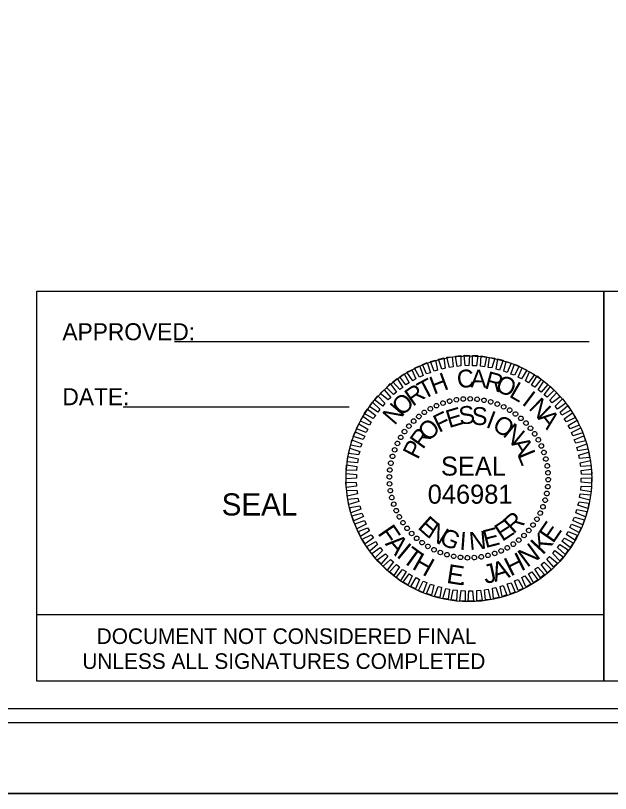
# Model space of a CAD drawing. Extents: x 198 to 2213, y -571 to 529.
# Drawn here: x 1292.9 to 1502.9, y -570.9 to -296.6 of the extents above; entities that cross this region are included whole.
import ezdxf

# ---------------------------------------------------------------- set-up
doc = ezdxf.new("R2010")
doc.units = 0
for name, color, linetype in [('DEV TRANSPORTATION OPERATIONS PLAN SHEET', 7, 'Continuous'), ('P_RDY_Terminator_Cell', 7, 'Continuous'), ('Sheet Data Field CELL', 7, 'Continuous'), ('Sheet PE Seal CELL', 7, 'Continuous'), ('Sheet_Title_CELL', 7, 'Continuous')]:
    doc.layers.add(name, color=color, linetype=linetype)

msp = doc.modelspace()

# ---------------------------------------------------------------- linework, layer by layer
at = {"layer": 'DEV TRANSPORTATION OPERATIONS PLAN SHEET'}
for p, q in [((1443.71, -433.19), (1443.71, -433.19)), ((1446.05, -432.52), (1446.05, -432.52)), ((1448.51, -432.07), (1448.51, -432.07)), ((1450.92, -431.74), (1450.92, -431.74)), ((1453.37, -431.68), (1453.37, -431.68)), ((1455.83, -431.85), (1455.83, -431.85)), ((1458.24, -432.24), (1458.24, -432.24)), ((1460.58, -432.74), (1460.58, -432.74)), ((1439.29, -435.2), (1439.29, -435.2)), ((1441.47, -434.09), (1441.47, -434.09)), ((1462.93, -433.53), (1462.93, -433.53)), ((1465.17, -434.53), (1465.17, -434.53)), ((1467.34, -435.65), (1467.34, -435.65)), ((1435.21, -437.89), (1435.21, -437.89)), ((1437.17, -436.49), (1437.17, -436.49)), ((1469.36, -437.05), (1469.36, -437.05)), ((1471.31, -438.56), (1471.31, -438.56)), ((1431.69, -441.29), (1431.69, -441.29)), ((1433.37, -439.56), (1433.37, -439.56)), ((1473.04, -440.23), (1473.04, -440.23)), ((1430.18, -443.25), (1430.18, -443.25)), ((1474.72, -442.08), (1474.72, -442.08)), ((1476.12, -444.03), (1476.12, -444.03)), ((1428.79, -445.26), (1428.79, -445.26)), ((1477.4, -446.16), (1477.4, -446.16)), ((1426.66, -449.68), (1426.66, -449.68)), ((1427.67, -447.44), (1427.67, -447.44)), ((1478.52, -448.34), (1478.52, -448.34)), ((1425.88, -452.02), (1425.88, -452.02)), ((1479.42, -450.57), (1479.42, -450.57)), ((1425.38, -454.37), (1425.38, -454.37)), ((1480.09, -452.92), (1480.09, -452.92)), ((1424.99, -456.77), (1424.99, -456.77)), ((1480.53, -455.38), (1480.53, -455.38)), ((1480.87, -457.78), (1480.87, -457.78)), ((1424.82, -459.23), (1424.82, -459.23)), ((1452.87, -459.74), (1452.87, -459.74)), ((1480.92, -460.24), (1480.92, -460.24)), ((1424.87, -461.69), (1424.87, -461.69)), ((1480.76, -462.7), (1480.76, -462.7)), ((1425.21, -464.09), (1425.21, -464.09)), ((1480.37, -465.1), (1480.37, -465.1)), ((1425.66, -466.55), (1425.66, -466.55)), ((1426.33, -468.9), (1426.33, -468.9)), ((1479.86, -467.45), (1479.86, -467.45)), ((1427.22, -471.14), (1427.22, -471.14)), ((1479.08, -469.79), (1479.08, -469.79)), ((1428.34, -473.31), (1428.34, -473.31)), ((1476.96, -474.21), (1476.96, -474.21)), ((1478.07, -472.03), (1478.07, -472.03)), ((1429.62, -475.44), (1429.62, -475.44)), ((1475.56, -476.22), (1475.56, -476.22)), ((1431.02, -477.39), (1431.02, -477.39)), ((1432.7, -479.24), (1432.7, -479.24)), ((1472.37, -479.91), (1472.37, -479.91)), ((1474.05, -478.18), (1474.05, -478.18)), ((1434.43, -480.91), (1434.43, -480.91)), ((1436.39, -482.42), (1436.39, -482.42)), ((1470.53, -481.59), (1470.53, -481.59)), ((1438.4, -483.82), (1438.4, -483.82)), ((1440.58, -484.94), (1440.58, -484.94)), ((1464.27, -485.39), (1464.27, -485.39)), ((1466.45, -484.27), (1466.45, -484.27)), ((1468.57, -482.98), (1468.57, -482.98)), ((1442.81, -485.94), (1442.81, -485.94)), ((1445.16, -486.73), (1445.16, -486.73)), ((1447.51, -487.23), (1447.51, -487.23)), ((1449.91, -487.62), (1449.91, -487.62)), ((1452.37, -487.79), (1452.37, -487.79)), ((1454.83, -487.73), (1454.83, -487.73)), ((1457.23, -487.4), (1457.23, -487.4)), ((1459.69, -486.95), (1459.69, -486.95)), ((1462.04, -486.28), (1462.04, -486.28))]:
    msp.add_line(p, q, dxfattribs=at)
for points in [[(1446.05, -420.62), (1445.16, -417.04), (1447, -416.87), (1447.39, -420.45)], [(1448.74, -420.28), (1448.12, -416.71), (1450.02, -416.48), (1450.08, -420.11)], [(1451.53, -420), (1451.25, -416.37), (1453.09, -416.43), (1452.87, -420.06)], [(1454.21, -420.06), (1454.21, -416.43), (1456.06, -416.48), (1455.55, -420.11)], [(1457.01, -420.23), (1457.23, -416.59), (1459.07, -416.93), (1458.35, -420.45)], [(1437.95, -422.85), (1436.5, -419.61), (1438.17, -418.94), (1439.35, -422.52)], [(1440.69, -421.96), (1439.4, -418.61), (1441.14, -418.1), (1441.86, -421.57)], [(1443.37, -421.23), (1442.2, -417.71), (1444.1, -417.32), (1444.54, -420.95)], [(1459.69, -420.67), (1460.19, -417.1), (1462.04, -417.38), (1461.03, -420.84)], [(1462.54, -421.29), (1463.1, -417.66), (1465, -418.1), (1463.71, -421.57)], [(1465.22, -422.01), (1466.06, -418.55), (1467.79, -419.11), (1466.39, -422.41)], [(1467.74, -423.02), (1469.02, -419.5), (1470.59, -420.17), (1469.02, -423.41)], [(1433.09, -425.37), (1431.02, -422.35), (1432.75, -421.46), (1434.15, -424.7)], [(1435.49, -424.03), (1433.7, -420.9), (1435.44, -420.11), (1436.72, -423.52)], [(1470.25, -424.08), (1471.65, -420.79), (1473.38, -421.57), (1471.48, -424.7)], [(1472.82, -425.37), (1474.33, -422.18), (1476.01, -423.13), (1473.88, -426.04)], [(1428.51, -428.44), (1426.1, -425.76), (1427.61, -424.59), (1429.57, -427.71)], [(1430.63, -426.76), (1428.56, -423.91), (1430.02, -422.85), (1431.86, -426.09)], [(1475, -426.88), (1476.96, -423.64), (1478.41, -424.81), (1476.23, -427.55)], [(1426.27, -430.17), (1423.81, -427.71), (1425.15, -426.37), (1427.33, -429.39)], [(1477.29, -428.55), (1479.36, -425.48), (1480.81, -426.71), (1478.35, -429.34)], [(1479.42, -430.29), (1481.71, -427.38), (1483.05, -428.72), (1480.48, -431.12)], [(1422.47, -434.25), (1419.57, -432.07), (1420.79, -430.62), (1423.25, -433.25)], [(1424.43, -432.13), (1421.58, -429.84), (1422.97, -428.55), (1425.32, -431.24)], [(1481.43, -432.24), (1483.83, -429.61), (1485.17, -430.96), (1482.27, -433.14)], [(1420.79, -436.38), (1417.78, -434.48), (1418.84, -432.86), (1421.52, -435.31)], [(1483.38, -434.25), (1485.95, -431.74), (1487.13, -433.25), (1484.17, -435.37)], [(1419.12, -438.61), (1415.99, -436.94), (1417.11, -435.37), (1420.01, -437.61)], [(1485.06, -436.43), (1487.8, -434.09), (1488.86, -435.71), (1485.73, -437.49)], [(1417.78, -441.01), (1414.59, -439.62), (1415.43, -437.89), (1418.45, -439.95)], [(1486.51, -438.72), (1489.47, -436.6), (1490.54, -438.28), (1487.29, -439.84)], [(1416.66, -443.59), (1413.19, -442.3), (1414.03, -440.57), (1417.22, -442.36)], [(1487.97, -441.18), (1491.09, -439.23), (1491.82, -440.96), (1488.64, -442.24)], [(1415.54, -446.04), (1412.08, -445.04), (1412.8, -443.31), (1416.16, -444.87)], [(1489.08, -443.59), (1492.38, -441.91), (1493.11, -443.7), (1489.64, -444.81)], [(1414.7, -448.73), (1411.24, -448), (1411.63, -446.16), (1415.15, -447.55)], [(1490.09, -446.21), (1493.5, -444.76), (1494.11, -446.49), (1490.65, -447.39)], [(1413.98, -451.41), (1410.51, -450.96), (1410.9, -449.06), (1414.42, -450.24)], [(1490.98, -448.89), (1494.56, -447.61), (1494.89, -449.45), (1491.37, -450.07)], [(1413.53, -454.26), (1409.95, -453.92), (1410.18, -452.02), (1413.81, -452.92)], [(1491.65, -451.58), (1495.17, -450.51), (1495.51, -452.41), (1491.99, -452.75)], [(1413.25, -456.94), (1409.62, -456.83), (1409.73, -454.99), (1413.36, -455.6)], [(1492.16, -454.26), (1495.79, -453.48), (1495.96, -455.38), (1492.38, -455.6)], [(1413.19, -459.74), (1409.56, -459.9), (1409.56, -458), (1413.19, -458.39)], [(1492.49, -456.94), (1496.12, -456.49), (1496.24, -458.39), (1492.6, -458.28)], [(1492.55, -459.74), (1496.18, -459.57), (1496.18, -461.47), (1492.55, -461.08)], [(1413.25, -462.53), (1409.62, -462.98), (1409.51, -461.08), (1413.14, -461.19)], [(1492.49, -462.53), (1496.12, -462.64), (1496.01, -464.49), (1492.38, -463.87)], [(1413.59, -465.21), (1409.95, -465.99), (1409.79, -464.09), (1413.36, -463.87)], [(1492.21, -465.21), (1495.79, -465.55), (1495.57, -467.45), (1491.93, -466.55)], [(1414.09, -467.89), (1410.57, -468.96), (1410.23, -467.06), (1413.75, -466.72)], [(1491.77, -468.06), (1495.23, -468.51), (1494.84, -470.41), (1491.32, -469.24)], [(1414.76, -470.58), (1411.18, -471.86), (1410.85, -470.02), (1414.37, -469.4)], [(1491.04, -470.74), (1494.5, -471.47), (1494.11, -473.31), (1490.59, -471.92)], [(1415.65, -473.26), (1412.24, -474.71), (1411.63, -472.98), (1415.09, -472.09)], [(1490.2, -473.43), (1493.67, -474.43), (1492.94, -476.16), (1489.59, -474.6)], [(1416.66, -475.89), (1413.36, -477.56), (1412.64, -475.77), (1416.1, -474.66)], [(1417.78, -478.29), (1414.65, -480.24), (1413.92, -478.51), (1417.11, -477.23)], [(1489.08, -475.89), (1492.55, -477.17), (1491.71, -478.9), (1488.52, -477.11)], [(1419.23, -480.75), (1416.27, -482.87), (1415.21, -481.19), (1418.45, -479.63)], [(1487.97, -478.46), (1491.15, -479.85), (1490.31, -481.59), (1487.29, -479.52)], [(1420.68, -483.04), (1417.94, -485.39), (1416.88, -483.76), (1420.01, -481.98)], [(1486.62, -480.86), (1489.75, -482.54), (1488.64, -484.1), (1485.73, -481.86)], [(1422.36, -485.22), (1419.79, -487.73), (1418.62, -486.22), (1421.58, -484.1)], [(1483.27, -485.22), (1486.18, -487.4), (1484.95, -488.85), (1482.49, -486.22)], [(1484.95, -483.09), (1487.97, -484.99), (1486.9, -486.61), (1484.22, -484.16)], [(1424.32, -487.23), (1421.91, -489.86), (1420.57, -488.51), (1423.48, -486.34)], [(1481.32, -487.34), (1484.17, -489.63), (1482.77, -490.92), (1480.42, -488.24)], [(1426.33, -489.19), (1424.04, -492.09), (1422.69, -490.75), (1425.27, -488.35)], [(1428.45, -490.92), (1426.38, -493.99), (1424.93, -492.76), (1427.39, -490.14)], [(1479.47, -489.3), (1481.93, -491.76), (1480.59, -493.1), (1478.41, -490.08)], [(1430.74, -492.59), (1428.79, -495.84), (1427.33, -494.66), (1429.51, -491.92)], [(1432.92, -494.1), (1431.41, -497.29), (1429.74, -496.34), (1431.86, -493.43)], [(1475.11, -492.71), (1477.18, -495.56), (1475.73, -496.62), (1473.88, -493.38)], [(1477.24, -491.03), (1479.64, -493.71), (1478.13, -494.89), (1476.17, -491.76)], [(1435.49, -495.39), (1434.09, -498.69), (1432.36, -497.9), (1434.26, -494.77)], [(1438.01, -496.45), (1436.72, -499.97), (1435.16, -499.3), (1436.72, -496.06)], [(1470.25, -495.44), (1472.04, -498.57), (1470.31, -499.36), (1469.02, -495.95)], [(1472.65, -494.1), (1474.72, -497.12), (1472.99, -498.01), (1471.59, -494.77)], [(1440.52, -497.46), (1439.68, -500.92), (1437.95, -500.36), (1439.35, -497.06)], [(1443.2, -498.18), (1442.64, -501.81), (1440.74, -501.37), (1442.03, -497.9)], [(1446.05, -498.8), (1445.55, -502.37), (1443.71, -502.09), (1444.71, -498.63)], [(1448.74, -499.24), (1448.51, -502.88), (1446.67, -502.54), (1447.39, -499.02)], [(1457.01, -499.19), (1457.62, -502.76), (1455.72, -502.99), (1455.67, -499.36)], [(1459.69, -498.85), (1460.58, -502.43), (1458.74, -502.6), (1458.35, -499.02)], [(1462.37, -498.24), (1463.54, -501.76), (1461.64, -502.15), (1461.2, -498.52)], [(1465.05, -497.51), (1466.34, -500.86), (1464.61, -501.37), (1463.88, -497.9)], [(1467.79, -496.62), (1469.24, -499.86), (1467.57, -500.53), (1466.39, -496.95)], [(1451.53, -499.41), (1451.53, -503.04), (1449.69, -502.99), (1450.19, -499.36)], [(1454.21, -499.47), (1454.49, -503.1), (1452.65, -503.04), (1452.87, -499.41)]]:
    msp.add_lwpolyline(points, close=True, dxfattribs=at)
for centre, major_axis in [((1441.47, -434.13), (-0.327, 0.735)), ((1443.75, -433.23), (-0.262, 0.761)), ((1446.09, -432.54), (-0.195, 0.781)), ((1448.49, -432.05), (-0.126, 0.795)), ((1450.92, -431.77), (-0.056, 0.803)), ((1453.36, -431.71), (0.014, 0.805)), ((1455.8, -431.86), (0.084, 0.8)), ((1458.22, -432.22), (0.154, 0.79)), ((1460.6, -432.79), (0.222, 0.774)), ((1462.92, -433.57), (0.288, 0.751)), ((1437.2, -436.5), (-0.45, 0.667)), ((1439.28, -435.22), (-0.39, 0.704)), ((1465.16, -434.54), (0.353, 0.723)), ((1467.31, -435.71), (0.414, 0.69)), ((1433.4, -439.57), (-0.559, 0.579)), ((1435.23, -437.95), (-0.506, 0.625)), ((1469.35, -437.06), (0.473, 0.651)), ((1471.26, -438.58), (0.528, 0.607)), ((1431.72, -441.35), (-0.607, 0.528)), ((1473.03, -440.26), (0.579, 0.559)), ((1474.65, -442.09), (0.625, 0.506)), ((1430.19, -443.26), (-0.651, 0.473)), ((1476.11, -444.06), (0.667, 0.45)), ((1427.68, -447.45), (-0.723, 0.353)), ((1428.84, -445.3), (-0.69, 0.414)), ((1477.39, -446.15), (0.704, 0.39)), ((1426.7, -449.69), (-0.751, 0.288)), ((1478.48, -448.33), (0.735, 0.327)), ((1479.37, -450.61), (0.761, 0.262)), ((1425.93, -452.01), (-0.774, 0.222)), ((1480.07, -452.95), (0.781, 0.195)), ((1425.36, -454.39), (-0.79, 0.154)), ((1480.56, -455.35), (0.795, 0.126)), ((1424.99, -456.81), (-0.8, 0.084)), ((1480.83, -457.78), (0.803, 0.056)), ((1424.84, -459.25), (-0.805, 0.014)), ((1480.9, -460.22), (0.805, -0.014)), ((1424.91, -461.69), (-0.803, -0.056)), ((1425.19, -464.12), (-0.795, -0.126)), ((1480.75, -462.67), (0.8, -0.084)), ((1425.67, -466.52), (-0.781, -0.195)), ((1480.39, -465.08), (0.79, -0.154)), ((1426.37, -468.86), (-0.761, -0.262)), ((1479.04, -469.78), (0.751, -0.288)), ((1479.82, -467.46), (0.774, -0.222)), ((1427.26, -471.14), (-0.735, -0.327)), ((1478.06, -472.02), (0.723, -0.353)), ((1428.35, -473.32), (-0.704, -0.39)), ((1429.63, -475.41), (-0.667, -0.45)), ((1476.9, -474.17), (0.69, -0.414)), ((1431.09, -477.38), (-0.625, -0.506)), ((1474.03, -478.12), (0.607, -0.528)), ((1475.55, -476.21), (0.651, -0.473)), ((1432.71, -479.21), (-0.579, -0.559)), ((1434.48, -480.89), (-0.528, -0.607)), ((1472.34, -479.9), (0.559, -0.579)), ((1436.4, -482.41), (-0.473, -0.651)), ((1468.55, -482.97), (0.45, -0.667)), ((1470.51, -481.52), (0.506, -0.625)), ((1438.43, -483.76), (-0.414, -0.69)), ((1440.58, -484.93), (-0.353, -0.723)), ((1442.83, -485.9), (-0.288, -0.751)), ((1462, -486.24), (0.262, -0.761)), ((1464.27, -485.34), (0.327, -0.735)), ((1466.46, -484.25), (0.39, -0.704)), ((1445.14, -486.68), (-0.222, -0.774)), ((1447.52, -487.25), (-0.154, -0.79)), ((1449.94, -487.61), (-0.084, -0.8)), ((1452.38, -487.76), (-0.014, -0.805)), ((1454.83, -487.7), (0.056, -0.803)), ((1457.26, -487.42), (0.126, -0.795)), ((1459.65, -486.93), (0.195, -0.781))]:
    msp.add_ellipse(centre, major_axis=major_axis, ratio=0.999708, dxfattribs=at)
at = {"layer": 'Sheet Data Field CELL'}
for points in [[(197.66, -570.86), (1885.65, -570.86), (1885.65, 529.13), (197.66, 529.13)], [(197.66, 529.13), (1885.65, 529.13), (1885.65, -570.86), (197.66, -570.86)]]:
    msp.add_lwpolyline(points, close=True, dxfattribs=at)
at = {"layer": 'Sheet PE Seal CELL'}
for p, q in [((1349.02, -411.49), (1495.36, -411.49)), ((1500.5, -417.31), (1500.51, -531.31)), ((1330.9, -434.57), (1410.69, -434.57)), ((938.42, -540.86), (1850.37, -540.86)), ((370.94, -545.86), (1850.37, -545.86))]:
    msp.add_line(p, q, dxfattribs=at)
for points in [[(1300.47, -393.81), (1500.5, -393.81), (1500.5, -531.31), (1300.47, -531.31)], [(1500.5, -393.81), (1614.51, -393.81), (1614.51, -531.31), (1500.5, -531.31)]]:
    msp.add_lwpolyline(points, close=True, dxfattribs=at)
msp.add_circle((1452.91, -459.9), 43.34, dxfattribs=at)
at = {"layer": 'Sheet_Title_CELL'}
for p, q in [((1300.47, -531.31), (1300.47, -507.81)), ((1300.47, -507.81), (1500.5, -507.81)), ((1500.5, -507.82), (1500.5, -531.32)), ((1500.5, -531.31), (1300.47, -531.31))]:
    msp.add_line(p, q, dxfattribs=at)

# ---------------------------------------------------------------- texts
at = {"layer": 'DEV TRANSPORTATION OPERATIONS PLAN SHEET'}
for s, height, rotation, p in [('C', 6.3, 6.2199, (1449.02, -428.05)), ('A', 6.3, 359.0203, (1453.43, -427.71)), ('R', 6.3, 344.6211, (1458.12, -427.94)), ('T', 6.3, 27.8198, (1436.89, -432.13)), ('H', 6.3, 20.6195, (1440.52, -430.29)), ('O', 6.3, 337.4212, (1461.87, -428.78)), ('R', 6.3, 35.0205, (1433.09, -434.59)), ('L', 6.3, 330.2209, (1466.79, -430.84)), ('O', 6.3, 42.2217, (1429.23, -438.05)), ('I', 6.3, 323.0201, (1471.31, -433.53)), ('N', 6.3, 49.4235, (1426.66, -441.29)), ('N', 6.3, 315.8189, (1473.72, -435.26)), ('F', 6.3, 25.967, (1442.31, -443.75)), ('E', 6.3, 16.6111, (1445.89, -442.08)), ('S', 6.3, 7.2556, (1449.74, -440.9)), ('S', 6.3, 357.9004, (1453.77, -440.85)), ('I', 6.3, 339.1896, (1458.57, -441.63)), ('O', 6.3, 329.8335, (1460.81, -442.41)), ('A', 6.3, 308.6172, (1477.01, -438.56)), ('O', 6.3, 44.6812, (1438.62, -447.05)), ('N', 6.3, 320.4766, (1464.55, -444.65)), ('R', 6.3, 54.0397, (1436.67, -449.79)), ('P', 6.3, 63.3989, (1434.88, -453.36)), ('A', 6.3, 301.7603, (1467.74, -447.55)), ('L', 6.3, 292.4009, (1469.92, -451.41)), ('SEAL', 6.704, 360, (1443.04, -458.79)), ('E', 6.3, 318.2769, (1434.54, -477.23)), ('E', 6.3, 33.1241, (1464.66, -482.2)), ('R', 6.3, 42.4814, (1468.63, -479.57)), ('F', 6.7, 304.4142, (1420.49, -479.12)), ('N', 6.3, 327.634, (1437.89, -480.24)), ('E', 6.3, 14.4118, (1458.74, -484.38)), ('E', 6.7, 55.493, (1482.6, -482.97)), ('G', 6.3, 336.9902, (1442.14, -482.76)), ('I', 6.3, 355.7012, (1449.46, -484.88)), ('N', 6.3, 5.0564, (1453.21, -485.05)), ('K', 6.7, 47.2091, (1478.94, -487.01)), ('A', 6.7, 311.4309, (1423.11, -482.93)), ('I', 6.7, 320.2712, (1427.02, -487.23)), ('N', 6.7, 36.4833, (1473.41, -491.39)), ('T', 6.7, 324.0731, (1428.9, -488.88)), ('H', 6.7, 330.8733, (1432.52, -491.52)), ('H', 6.7, 26.4993, (1467.61, -494.47)), ('E', 6.7, 351.0577, (1444.74, -496.58)), ('J', 6.7, 12.4012, (1458.71, -497.02)), ('A', 6.7, 17.659, (1462.1, -496.33)), ('.', 6.7, 358.167, (1449.36, -497.31))]:
    msp.add_text(s, height=height, rotation=rotation, dxfattribs=at).set_placement(p)
msp.add_text('046981', height=6.704, dxfattribs=at).set_placement((1438.37, -468.69))
at = {"layer": 'P_RDY_Terminator_Cell'}
msp.add_text('SEAL', height=7.812, dxfattribs=at).set_placement((1365.64, -472.86))
at = {"layer": 'Sheet PE Seal CELL'}
for s, p in [('APPROVED:  ', (1309.44, -411.06)), ('DATE:  ', (1309.44, -433.97))]:
    msp.add_text(s, height=6, dxfattribs=at).set_placement(p)
at = {"layer": 'Sheet_Title_CELL'}
for s, p in [('DOCUMENT NOT CONSIDERED FINAL', (1321.54, -518.16)), ('UNLESS ALL SIGNATURES COMPLETED', (1316.47, -526.96))]:
    msp.add_text(s, height=5.5, dxfattribs=at).set_placement(p)

doc.saveas('drawing.dxf')
